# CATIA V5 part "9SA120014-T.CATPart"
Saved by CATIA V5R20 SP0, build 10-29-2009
Part number: 9SA120014-T
Revision: ANY
Definition: UNKNOWN
Nomenclature: 9SA120014-T
Source: Unknown
Bounding box of the stored display mesh (mm): x -4.5 to 4.5, y 0 to 5.95, z -4.5 to 4.5
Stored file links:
  C:\Users\Utente\Desktop\IO LAVORO\3D X SITO CF\CUMSA\3D files SA\SA 120014\9SA120014-T.CATPart
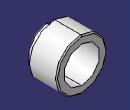
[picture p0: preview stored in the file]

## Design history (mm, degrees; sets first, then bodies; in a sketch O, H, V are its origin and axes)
Body1 "Chaflán1" (main body)
  Solid1: solid without history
